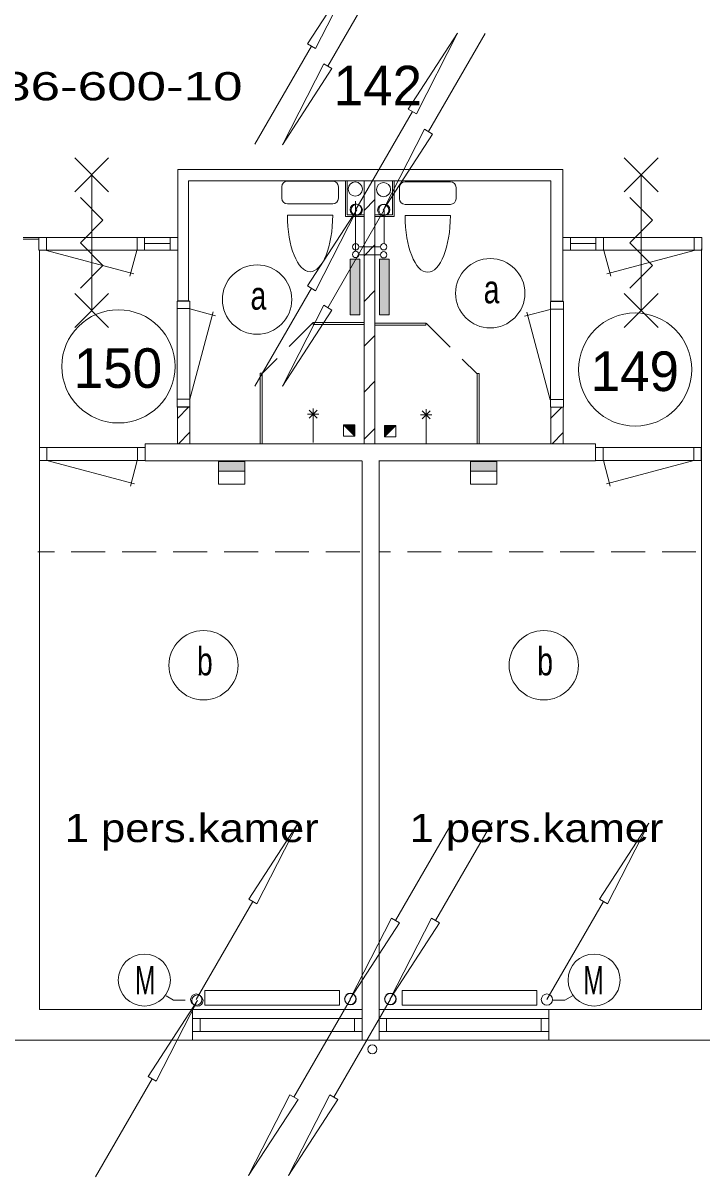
# Model space of a CAD drawing. Extents: x 295824 to 414724, y 24924 to 109024.
# Drawn here: x 313944 to 319942, y 61088 to 71286 of the extents above; entities that cross this region are included whole.
import ezdxf
from ezdxf.enums import TextEntityAlignment as Align

# ---------------------------------------------------------------- set-up
doc = ezdxf.new("R2010")
doc.units = 0
doc.header["$LTSCALE"] = 100
doc.linetypes.add('LONG_DASHED', pattern=[7.5, 6, -1.5])
doc.linetypes.add('MEDIUM_DASHED', pattern=[4.5, 3, -1.5])
doc.layers.add('16', color=7, linetype='Continuous', lineweight=13)
doc.layers.add('61', color=7, linetype='Continuous', lineweight=13)

msp = doc.modelspace()

# ---------------------------------------------------------------- hatches: boundary and pattern name
at = {"layer": '16'}
for points in [[(316835.4, 68706.6), (316920.8, 68706.6), (316920.8, 69198.8), (316835.4, 69198.8)], [(317094.6, 68706.6), (317180, 68706.6), (317180, 69198.8), (317094.6, 69198.8)], [(315902.2, 67410.5), (315670.7, 67410.5), (315670.7, 67324), (315902.2, 67324)], [(318129.9, 67410.5), (317898.4, 67410.5), (317898.4, 67324), (318129.9, 67324)]]:
    msp.add_hatch(color=256, dxfattribs=at).paths.add_polyline_path(points)
at = {"layer": '61'}
for points in [[(316775.3, 67734.4), (316875.3, 67634.4), (316875.3, 67734.4)], [(317237.7, 67729), (317137.7, 67629), (317137.7, 67729)]]:
    msp.add_hatch(color=256, dxfattribs=at).paths.add_polyline_path(points)

# ---------------------------------------------------------------- linework, layer by layer
at = {"layer": '16'}
for p, q in [((317136.2, 71769.9), (316636.2, 70903.9)), ((318027.2, 71192.1), (317527.2, 70326.1)), ((315992.3, 70215), (316492.3, 71081)), ((316884.2, 69637.9), (317384.2, 70503.9)), ((316882.7, 69712.6), (316882.7, 69273)), ((317136.2, 69636.2), (316636.2, 68770.2)), ((317103, 69237.6), (316911.2, 69237.6)), ((315992.3, 68075.4), (316492.3, 68941.4)), ((315670.7, 67324), (315670.7, 67210.1)), ((317898.4, 67324), (317898.4, 67210.1)), ((317735.5, 64220.2), (317235.5, 63354.2)), ((318088.9, 64220.2), (317588.9, 63354.2)), ((315474.7, 62655.3), (315974.7, 63521.3)), ((318573.2, 62655.3), (319073.2, 63521.3)), ((316837.4, 62658.9), (316337.4, 61792.9)), ((317190.8, 62658.9), (316690.8, 61792.9)), ((314584.5, 61087.9), (315084.5, 61953.9))]:
    msp.add_line(p, q, dxfattribs=at)
at = {"layer": '16', "linetype": 'LONG_DASHED'}
for p, q in [((317133.8, 69631.8), (317133.8, 69334.1)), ((316911.4, 69308.4), (317102.9, 69308.4))]:
    msp.add_line(p, q, dxfattribs=at)
at = {"layer": '16'}
for points in [[(316892.3, 71774), (316528.3, 71060), (316456.3, 71102)], [(317784.2, 71196.9), (317420.2, 70482.9), (317348.2, 70524.9)], [(316236.2, 70210.9), (316600.2, 70924.9), (316672.2, 70882.9)], [(317127.2, 69633.1), (317491.2, 70347.1), (317563.2, 70305.1)], [(316892.3, 69634.4), (316528.3, 68920.4), (316456.3, 68962.4)], [(316835.4, 68706.6), (316920.8, 68706.6), (316920.8, 69198.8), (316835.4, 69198.8)], [(317094.6, 68706.6), (317180, 68706.6), (317180, 69198.8), (317094.6, 69198.8)], [(316236.2, 68077.2), (316600.2, 68791.2), (316672.2, 68749.2)], [(315902.2, 67410.5), (315670.7, 67410.5), (315670.7, 67324), (315902.2, 67324)], [(318129.9, 67410.5), (317898.4, 67410.5), (317898.4, 67324), (318129.9, 67324)], [(316374.7, 64214.3), (316010.7, 63500.3), (315938.7, 63542.3)], [(319473.2, 64214.3), (319109.2, 63500.3), (319037.2, 63542.3)], [(316835.5, 62661.2), (317199.5, 63375.2), (317271.5, 63333.2)], [(317188.9, 62661.2), (317552.9, 63375.2), (317624.9, 63333.2)], [(315551.6, 62606.4), (316741.5, 62606.4), (316741.5, 62736), (315551.6, 62736)], [(317295.2, 62606.4), (318485.2, 62606.4), (318485.2, 62736), (317295.2, 62736)], [(315484.5, 62646.9), (315120.5, 61932.9), (315048.5, 61974.9)], [(315937.4, 61099.9), (316301.4, 61813.9), (316373.4, 61771.9)], [(316290.8, 61099.9), (316654.8, 61813.9), (316726.8, 61771.9)]]:
    msp.add_lwpolyline(points, close=True, dxfattribs=at)
for points in [[(315902.2, 67324), (315902.2, 67210.1), (315670.7, 67210.1)], [(318129.9, 67324), (318129.9, 67210.1), (317898.4, 67210.1)], [(315376.1, 62650.1), (315273.6, 62650.1), (315207.1, 62688.4)], [(318628.8, 62650.1), (318731.4, 62650.1), (318797.8, 62688.4)]]:
    msp.add_lwpolyline(points, dxfattribs=at)
for centre, radius in [((316884.2, 69637.5), 50), ((316892.3, 69634.1), 50), ((317127.2, 69633.4), 50), ((317136.2, 69636.5), 50), ((316883.5, 69308.4), 27.9), ((316883.5, 69240.6), 27.9), ((317130.9, 69308.4), 27.9), ((317130.9, 69237.6), 27.9), ((315015.6, 62828.1), 229.9), ((318989.4, 62828.1), 229.9), ((315474.7, 62655), 50), ((315484.5, 62646.6), 50), ((316835.5, 62661.5), 50), ((316837.4, 62659.2), 50), ((317188.9, 62661.5), 50), ((317190.8, 62659.2), 50), ((318573.2, 62655), 50)]:
    msp.add_circle(centre, radius, dxfattribs=at)
at = {"layer": '61'}
for p, q in [((314400.3, 69794.2), (314700.3, 70094.2)), ((314700.3, 69794.2), (314400.3, 70094.2)), ((319256.2, 69794.2), (319556.2, 70094.2)), ((319556.2, 69794.2), (319256.2, 70094.2)), ((314550.3, 69944.2), (314550.3, 68744.2)), ((315407, 68829.5), (315407, 69891.5)), ((316280.2, 69888.5), (316680.2, 69888.5)), ((316807, 69591.5), (316807, 69891.5)), ((316957, 67566.5), (316957, 69891.5)), ((317053.3, 67566.5), (317053.3, 69891.5)), ((317207.1, 69891), (317207.1, 69591)), ((317319.6, 69883.6), (317719.6, 69883.6)), ((319406.2, 69944.2), (319406.2, 68744.2)), ((316230.2, 69738.5), (316230.2, 69838.5)), ((316730.2, 69838.5), (316730.2, 69738.5)), ((317269.6, 69733.6), (317269.6, 69833.6)), ((317769.6, 69833.6), (317769.6, 69733.6)), ((316680.2, 69688.5), (316280.2, 69688.5)), ((317052.8, 69725.6), (316957, 69629.8)), ((317719.6, 69683.6), (317319.6, 69683.6)), ((316280.2, 69588.5), (316680.2, 69588.5)), ((316957, 69591.5), (316807, 69591.5)), ((317207.1, 69591), (317057.1, 69591)), ((317319.6, 69583.6), (317719.6, 69583.6)), ((313944.8, 69391.4), (314086, 69391.4)), ((313944.8, 69376.4), (314086, 69376.4)), ((314150.8, 69391.4), (314150.8, 69277.4)), ((314950.8, 69391.4), (314950.8, 69277.4)), ((315017.8, 69391.4), (315017.8, 69277.4)), ((315243.8, 69391.4), (315243.8, 69277.4)), ((318712.3, 68828), (318712.3, 69393.9)), ((318780.5, 69391.4), (318780.5, 69277.4)), ((319006.5, 69391.4), (319006.5, 69277.4)), ((319073.5, 69391.4), (319073.5, 69277.4)), ((319873.5, 69391.4), (319873.5, 69277.4)), ((314090.1, 69276.6), (314090.1, 62566.5)), ((314150.1, 69276.8), (314922.8, 69069.7)), ((314948.5, 69276.2), (314887.7, 69049.3)), ((315243.8, 69337.3), (315017.8, 69337.3)), ((315312.3, 68829.5), (315312.3, 69291.5)), ((317052.8, 69324.7), (316957, 69228.9)), ((318780.5, 69337.4), (319006.5, 69337.4)), ((319075.8, 69276.2), (319136.6, 69049.3)), ((319874.2, 69276.8), (319101.5, 69069.8)), ((319940.1, 69291.5), (319940.1, 62566.5)), ((314400.3, 68594.2), (314700.3, 68894.2)), ((314700.3, 68594.2), (314400.3, 68894.2)), ((317052.8, 68921.3), (316957, 68825.5)), ((319256.2, 68594.2), (319556.2, 68894.2)), ((319556.2, 68594.2), (319256.2, 68894.2)), ((315304.8, 67894.7), (315304.8, 68828.7)), ((315304.8, 68761.7), (315418.8, 68761.7)), ((315407, 68829.5), (315312.3, 68829.5)), ((315416.8, 67960.9), (315623.9, 68733.6)), ((315417.5, 68759.3), (315644.3, 68698.5)), ((318600.4, 68755.1), (318373.6, 68694.3)), ((318718.2, 68757.4), (318604.2, 68757.4)), ((318712.3, 68828), (318607, 68828)), ((318718.2, 67892), (318718.2, 68824.4)), ((316958.1, 68640.1), (316508.7, 68640.1)), ((316508.7, 68640.1), (316508.7, 68622.1)), ((317054.8, 68634.8), (317504.3, 68634.8)), ((317504.3, 68634.8), (317504.3, 68616.8)), ((318601, 67956.6), (318394, 68729.4)), ((316957.8, 68622.1), (316508.7, 68622.1)), ((317055.2, 68616.8), (317504.3, 68616.8)), ((317052.8, 68525.3), (316957, 68429.5)), ((316057.8, 67572.1), (316057.8, 68192.6)), ((317955.2, 67566.7), (317955.2, 68187.2)), ((317052.8, 68120.7), (316957, 68024.9)), ((315304.8, 67961.7), (315418.8, 67961.7)), ((318718.2, 67957.4), (318604.2, 67957.4)), ((315418.2, 67894.7), (315304.2, 67894.7)), ((315417.5, 67891.1), (315307.5, 67891.1)), ((315307.5, 67891.1), (315307.5, 67567.1)), ((315407.2, 67889.9), (315307.5, 67790.2)), ((315417.5, 67891.1), (315417.5, 67567.1)), ((316557.6, 67828.6), (316457.6, 67828.6)), ((316543, 67793.2), (316472.3, 67863.9)), ((316543, 67863.9), (316472.3, 67793.2)), ((316507.6, 67778.6), (316507.6, 67878.6)), ((317455.3, 67823.2), (317555.3, 67823.2)), ((317470, 67787.9), (317540.7, 67858.6)), ((317470, 67858.6), (317540.7, 67787.9)), ((317505.3, 67773.2), (317505.3, 67873.2)), ((318705.6, 67889.9), (318605.9, 67790.2)), ((318716.4, 67891.1), (318606.5, 67891.1)), ((318606.5, 67891.1), (318606.5, 67567.1)), ((318716.4, 67891.1), (318716.4, 67567.1)), ((316507.6, 67778.6), (316507.6, 67578.6)), ((317505.3, 67773.2), (317505.3, 67573.2)), ((315415.8, 67667.3), (315316.1, 67567.6)), ((317052.8, 67702.6), (316957, 67606.8)), ((318717.9, 67667.3), (318618.2, 67567.6)), ((314155.4, 67534), (314155.4, 67420)), ((314955.4, 67534), (314955.4, 67420)), ((315022.4, 67534), (315022.4, 67420)), ((315417.5, 67567.1), (315307.5, 67567.1)), ((318716.4, 67567.1), (318606.5, 67567.1)), ((319003.1, 67535.1), (319003.1, 67421.1)), ((319070.1, 67535.1), (319070.1, 67421.1)), ((319870.1, 67535.1), (319870.1, 67421.1)), ((314154.6, 67419.4), (314927.4, 67212.3)), ((314953.1, 67418.7), (314892.3, 67191.9)), ((316940.1, 62296.5), (316940.1, 67416.5)), ((317090.1, 62296.5), (317090.1, 67416.5)), ((319072.4, 67419.8), (319133.2, 67193)), ((319870.8, 67420.4), (319098.1, 67213.4)), ((314090.1, 62566.5), (316940.1, 62566.5)), ((315441, 62295.2), (315441, 62565.2)), ((319940.1, 62566.5), (317090.1, 62566.5)), ((318589.5, 62295.3), (318589.5, 62565.3)), ((315508, 62373.6), (315508, 62487.5)), ((316873.1, 62373), (316873.1, 62487)), ((317156.6, 62373.9), (317156.6, 62487.9)), ((318520.9, 62373.6), (318520.9, 62487.3)), ((326233, 62296.5), (307806, 62296.5))]:
    msp.add_line(p, q, dxfattribs=at)
at = {"layer": '61', "linetype": 'MEDIUM_DASHED'}
for p, q in [((316506.6, 68639.6), (316059.7, 68192.8)), ((317506.4, 68634.3), (317953.2, 68187.4)), ((316920.4, 66613.1), (314073.3, 66613.1)), ((319889.8, 66613.1), (317090.1, 66613.1))]:
    msp.add_line(p, q, dxfattribs=at)
at = {"layer": '61'}
for points in [[(318712.3, 69391.5), (318712.3, 69991.5), (315312.3, 69991.5), (315312.3, 69391.5)], [(318607, 68828), (318607, 69891.5), (315407, 69891.5)], [(316957, 69576.5), (316792, 69576.5), (316792, 69891.5)], [(317222.1, 69891), (317222.1, 69576), (317057.1, 69576)], [(314450.3, 69744.2), (314650.3, 69544.2), (314450.3, 69344.2), (314650.3, 69144.2), (314450.3, 68944.2)], [(319306.2, 69744.2), (319506.2, 69544.2), (319306.2, 69344.2), (319506.2, 69144.2), (319306.2, 68944.2)], [(316039.8, 67572.1), (316039.8, 68192.6), (316057.8, 68192.6)], [(317973.2, 67566.7), (317973.2, 68187.2), (317955.2, 68187.2)], [(316875.3, 67634.4), (316875.3, 67734.4), (316775.3, 67734.4)], [(317137.7, 67629), (317137.7, 67729), (317237.7, 67729)], [(314088.4, 67534), (314088.4, 67420), (315022.4, 67420)], [(315022.4, 67534), (314088.4, 67534), (314088.4, 67420)], [(317087.3, 67416.5), (319002.3, 67416.5), (319002.3, 67566.5), (315022.9, 67566.5)], [(316937.3, 67416.5), (315022.9, 67416.5), (315022.9, 67566.5)], [(319937.1, 67535.1), (319937.1, 67421.1), (319003.1, 67421.1)], [(319003.1, 67535.1), (319937.1, 67535.1), (319937.1, 67421.1)]]:
    msp.add_lwpolyline(points, dxfattribs=at)
for points in [[(315310.8, 69391.4), (315310.8, 69277.4), (314083.8, 69277.4), (314083.8, 69391.4)], [(315310.9, 69391.4), (315310.9, 69277.4), (314083.9, 69277.4), (314083.9, 69391.4)], [(319940.5, 69391.4), (319940.5, 69277.4), (318714.1, 69277.4), (318714.1, 69391.4)], [(319940.5, 69391.4), (319940.5, 69277.4), (318714.1, 69277.4), (318714.1, 69391.4)], [(315304.8, 67894.7), (315304.8, 68828.7), (315418.8, 68828.7), (315418.8, 67894.7)], [(318718.2, 68825.4), (318604.2, 68825.4), (318604.2, 67891.4), (318718.2, 67891.4)], [(316875.3, 67634.4), (316775.3, 67634.4), (316775.3, 67734.4)], [(316775.3, 67734.4), (316875.3, 67634.4), (316875.3, 67734.4)], [(317137.7, 67629), (317237.7, 67629), (317237.7, 67729)], [(317237.7, 67729), (317137.7, 67629), (317137.7, 67729)], [(315441.2, 62373.5), (315441.2, 62487.5), (316939.9, 62487.5), (316939.9, 62373.5)], [(317090.2, 62373.6), (317090.2, 62487.6), (318589.6, 62487.6), (318589.6, 62373.6)]]:
    msp.add_lwpolyline(points, close=True, dxfattribs=at)
for centre, radius in [((316879.5, 69819.1), 62.5), ((317129.5, 69813.5), 62.5), ((316011.8, 68842), 306.3), ((318072, 68897.8), 306.3), ((314786.6, 68251.4), 500), ((319352.5, 68223.6), 500), ((315538.5, 65610.1), 306.3), ((318545.3, 65610.1), 306.3), ((317029.6, 62216.3), 40)]:
    msp.add_circle(centre, radius, dxfattribs=at)
for centre, start, end in [((316280.2, 69838.5), 90, 180), ((316680.2, 69838.5), 0, 90), ((317319.6, 69833.6), 90, 180), ((317719.6, 69833.6), 0, 90), ((316280.2, 69738.5), 180, 270), ((316680.2, 69738.5), 270, 0), ((317319.6, 69733.6), 180, 270), ((317719.6, 69733.6), 270, 0)]:
    msp.add_arc(centre, 50, start, end, dxfattribs=at)
for centre in [(316480.2, 69588.5), (317519.6, 69583.6)]:
    msp.add_ellipse(centre, major_axis=(0, -500), ratio=0.4, start_param=4.712389, end_param=7.8539816, dxfattribs=at)

# ---------------------------------------------------------------- texts
at = {"layer": '16'}
for s, width, p in [('14x 486-600-10', 1.4, (312605.1, 70602.4)), ('M', 0.65, (314933.3, 62701.4)), ('M', 0.65, (318894.5, 62701.4))]:
    msp.add_text(s, height=250, dxfattribs=dict(at, width=width)).set_placement(p)
at = {"layer": '61'}
for s, p in [('142', (317079.2, 70558.3)), ('150', (314782.3, 68061.6)), ('149', (319349.6, 68033.7))]:
    msp.add_text(s, height=350, dxfattribs=at).set_placement(p, align=Align.CENTER)
for s, width, p in [('a', 0.75, (315953.8, 68752.8)), ('a', 0.75, (318014, 68808.6)), ('b', 0.75, (315480.5, 65520.9)), ('b', 0.75, (318487.3, 65520.9)), ('1 pers.kamer', 1.15, (314312.6, 64046.9)), ('1 pers.kamer', 1.15, (317359.4, 64046.9))]:
    msp.add_text(s, height=250, dxfattribs=dict(at, width=width)).set_placement(p)

doc.saveas('drawing.dxf')
